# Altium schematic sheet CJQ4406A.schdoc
size 127 x 101 mm
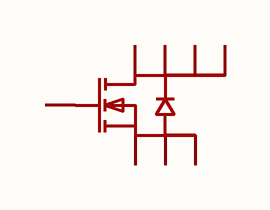
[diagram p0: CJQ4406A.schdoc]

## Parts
Q?  cjq4406a  [SOP-8_L4.9-W3.9-P1.27-LS6.0-BL]  (value not drawn)

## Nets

Not connected (* = marked no-connect by the designer): Q? 1(S) 2(S) 3(S) 4(G) 5(D) 6(D) 7(D) 8(D)

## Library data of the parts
Q? = cjq4406a: 数量:1个N沟道;漏源电压(Vdss):30V;连续漏极电流(Id):10A;导通电阻(RDS(on)):8.3mΩ@10V;耗散功率(Pd):2.5W;阈值电压(Vgs(th)):1V;; Manufacturer: CJ(江苏长电/长晶); AddInBom: yes; ModelId: 75c24a7891ee4dd6bdac16a7163ff87e; ModelName: SOP-8_L4.9-W3.9-P1.27-LS6.0-BL-1; ModelTransform: 192.913,236.22,0,0,0,0,-0.393,2.749,0; Number: 1个N沟道; Drain to Source Voltage: 30V; Current - Continuous Drain(Id): 10A; Pd - Power Dissipation: 2.5W; Gate Threshold Voltage (Vgs(th)): 1V; Gate Charge(Qg): 21.6nC@10V; Input Capacitance(Ciss): 1.28nF; Reverse Transfer Capacitance (Crss@Vds): 121pF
